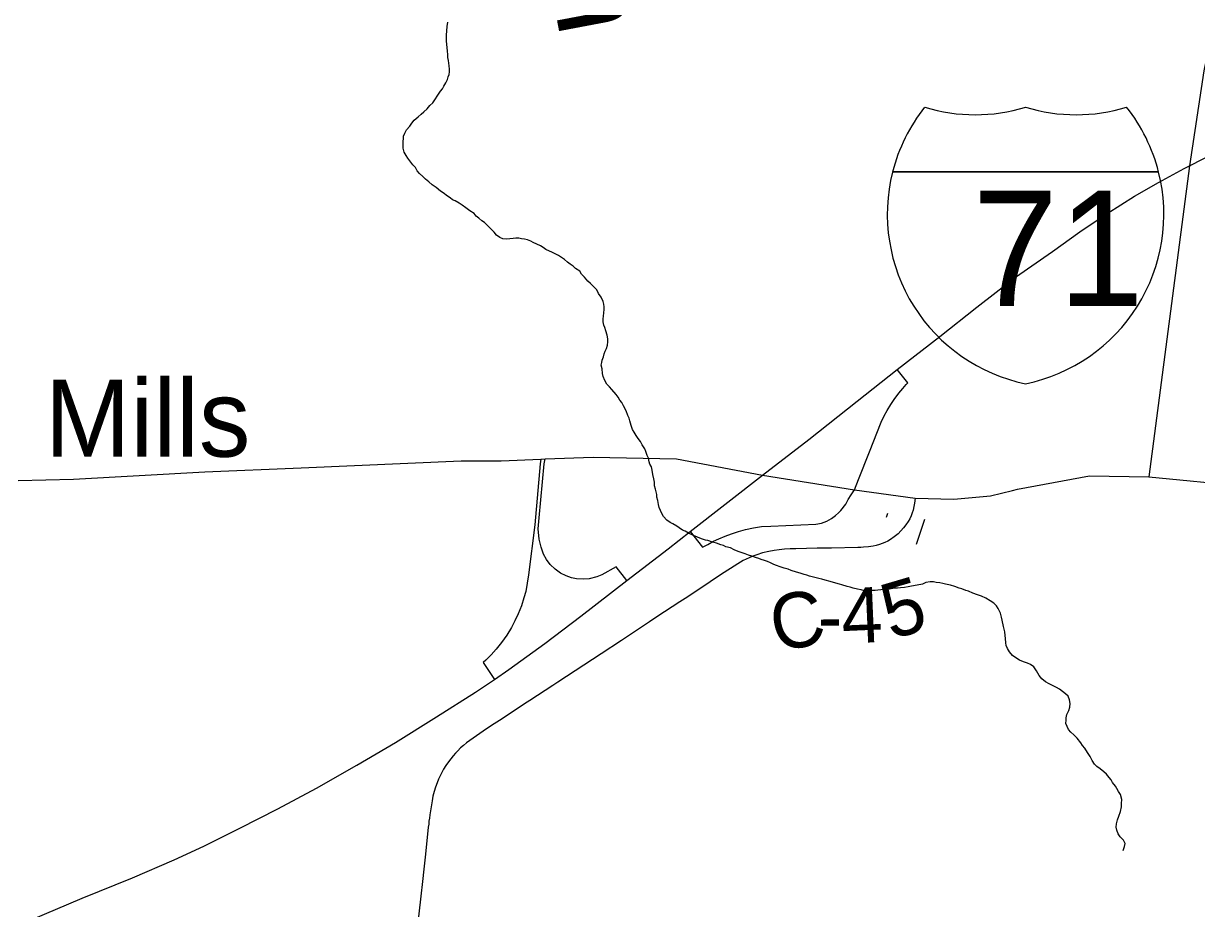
# Model space of a CAD drawing. Extents: x 0.4 to 34.4, y -2.1 to 19.9.
# Drawn here: x 4.197 to 5.402, y 14.193 to 15.102 of the extents above; entities that cross this region are included whole.
import ezdxf

# ---------------------------------------------------------------- set-up
doc = ezdxf.new("R2010")
doc.units = 0
for name, color, linetype in [('GM_X_County_Road', 7, 'Continuous'), ('GM_X_County_Road_Text', 7, 'Continuous'), ('GM_X_Interchange_Ramps', 7, 'Continuous'), ('GM_X_Interstate_Route', 7, 'Continuous'), ('GM_X_Interstate_Shield', 7, 'Continuous'), ('GM_X_Minor_River', 7, 'Continuous'), ('GM_X_Minor_River_Text', 7, 'Continuous'), ('GM_X_Unincorporated_Text', 7, 'Continuous')]:
    doc.layers.add(name, color=color, linetype=linetype)

msp = doc.modelspace()

# ---------------------------------------------------------------- linework, layer by layer
at = {"layer": 'GM_X_County_Road'}
for points in [[(5.1472, 16.0652), (5.1472, 16.0652), (5.1927, 15.4283), (5.1962, 15.413), (5.2017, 15.4034), (5.2182, 15.394), (5.4257, 15.3499), (5.4355, 15.3459), (5.4407, 15.3424), (5.4524, 15.2606), (5.4094, 15.0538), (5.3948, 14.9559)], [(5.3948, 14.9559), (5.3532, 14.6364)], [(5.3532, 14.6364), (5.551, 14.6173), (5.7946, 14.5981), (5.9549, 14.5868), (6.1689, 14.5743), (6.183, 14.58), (6.2787, 14.5749), (6.327, 14.5697), (6.3748, 14.5632), (6.4792, 14.5513), (6.6022, 14.5578), (6.6586, 14.5646), (6.9447, 14.6216), (6.9686, 14.6277), (7.0369, 14.6701), (7.058, 14.675), (7.1535, 14.6887)], [(4.191, 14.6326), (4.2481, 14.634), (4.383, 14.6414), (4.4819, 14.6455), (4.6462, 14.6527), (4.6594, 14.6528)], [(4.6594, 14.6528), (4.6875, 14.6529), (4.7282, 14.6546), (4.7326, 14.6548), (4.782, 14.6567), (4.8677, 14.6547), (4.9561, 14.6381)], [(4.9561, 14.6381), (5.0504, 14.6229), (5.1129, 14.6146), (5.1527, 14.6133), (5.1905, 14.617), (5.2131, 14.6224)], [(5.2131, 14.6224), (5.218, 14.6236), (5.2919, 14.6374), (5.3532, 14.6364)], [(5.1129, 14.6146), (5.1123, 14.6094), (5.1117, 14.6057), (5.1109, 14.6021), (5.1099, 14.5992), (5.1088, 14.5963), (5.1073, 14.5933), (5.1056, 14.5903), (5.1034, 14.587), (5.101, 14.5838), (5.0982, 14.5807), (5.0953, 14.5778), (5.0915, 14.5747), (5.0876, 14.572), (5.0847, 14.5703), (5.0819, 14.5689), (5.0791, 14.5677), (5.0761, 14.5667), (5.073, 14.5658), (5.0698, 14.565), (5.0648, 14.5643), (5.0597, 14.564), (5.0572, 14.5638), (5.0541, 14.5637), (5.0269, 14.5631), (5.0122, 14.5629), (4.9903, 14.5625), (4.9843, 14.5623), (4.9788, 14.5621), (4.9733, 14.5615), (4.9679, 14.5608), (4.9625, 14.5597), (4.9561, 14.5581), (4.9502, 14.5563), (4.9461, 14.5548), (4.9422, 14.5531), (4.9363, 14.5502), (4.9306, 14.5468), (4.9128, 14.5355), (4.9024, 14.5285), (4.8998, 14.5268), (4.8764, 14.5113), (4.8711, 14.5078), (4.8476, 14.4924), (4.845, 14.4906), (4.8424, 14.4889), (4.8398, 14.4872), (4.8163, 14.4717), (4.8111, 14.4683), (4.7902, 14.4546), (4.7457, 14.4254), (4.7405, 14.422), (4.717, 14.4065), (4.7143, 14.4048), (4.6856, 14.386), (4.6803, 14.3826), (4.6777, 14.3809), (4.6751, 14.3791), (4.6725, 14.3774), (4.6552, 14.3654), (4.6519, 14.363), (4.6488, 14.3604), (4.6457, 14.3577), (4.6428, 14.3549), (4.6404, 14.3523), (4.638, 14.3495), (4.6356, 14.3466), (4.6334, 14.3436), (4.6306, 14.3396), (4.6283, 14.3358), (4.6265, 14.3326), (4.6248, 14.3292), (4.6232, 14.3256), (4.6217, 14.3219), (4.62, 14.3174), (4.6186, 14.3128), (4.6174, 14.3081), (4.6165, 14.3033), (4.6141, 14.2888), (4.6137, 14.2857), (4.6133, 14.2826), (4.613, 14.2795), (4.6126, 14.2764), (4.6096, 14.2485), (4.6089, 14.2423), (4.6086, 14.2392), (4.606, 14.2144), (4.6057, 14.2114), (4.6046, 14.2022), (4.6014, 14.1754)]]:
    msp.add_lwpolyline(points, dxfattribs=at)
at = {"layer": 'GM_X_Interchange_Ramps'}
for points in [[(5.0504, 14.6229), (5.0547, 14.6335), (5.0661, 14.6621), (5.0779, 14.6924), (5.0811, 14.6989), (5.0841, 14.7045), (5.0878, 14.7106), (5.0914, 14.716), (5.0961, 14.7223), (5.1002, 14.7272), (5.1038, 14.7312), (5.1054, 14.7328), (5.0943, 14.7467)], [(4.7282, 14.6546), (4.7274, 14.6498), (4.7219, 14.587), (4.7157, 14.5356), (4.7127, 14.5186), (4.7109, 14.5119), (4.7082, 14.5037), (4.7049, 14.4954), (4.7016, 14.4882), (4.698, 14.4815), (4.6932, 14.4736), (4.6879, 14.466), (4.6825, 14.4593), (4.6773, 14.4535), (4.6717, 14.4478), (4.6689, 14.4454), (4.6805, 14.4282)], [(4.8166, 14.5299), (4.8057, 14.544), (4.7909, 14.5356), (4.7858, 14.5335), (4.7779, 14.5316), (4.7717, 14.5311), (4.765, 14.5315), (4.7599, 14.5326), (4.7543, 14.5345), (4.7484, 14.5375), (4.743, 14.5414), (4.7379, 14.5464), (4.7341, 14.5515), (4.731, 14.557), (4.7286, 14.5639), (4.7264, 14.5722), (4.7255, 14.5828), (4.7265, 14.5943), (4.7317, 14.6497), (4.7326, 14.6548)], [(4.8818, 14.5802), (4.8945, 14.5639), (4.8997, 14.5669), (4.9058, 14.5701), (4.9111, 14.5726), (4.9176, 14.5754), (4.9243, 14.5779), (4.9314, 14.5802), (4.9385, 14.5821), (4.9467, 14.5839), (4.9549, 14.5853), (4.9646, 14.5858), (5.011, 14.5877), (5.0165, 14.5888), (5.0221, 14.5909), (5.027, 14.5935), (5.031, 14.5965), (5.034, 14.5992), (5.0364, 14.6018), (5.0415, 14.6083), (5.0442, 14.6132), (5.0473, 14.618), (5.0504, 14.6229)]]:
    msp.add_lwpolyline(points, dxfattribs=at)
at = {"layer": 'GM_X_Interstate_Route'}
for points in [[(4.9561, 14.6381), (5.0038, 14.6747), (5.0534, 14.714), (5.0943, 14.7467), (5.1381, 14.7806), (5.1763, 14.8109), (5.216, 14.8416), (5.2541, 14.8681), (5.2823, 14.8883), (5.3101, 14.907), (5.3383, 14.9249), (5.3631, 14.939), (5.3894, 14.9532), (5.3948, 14.9559), (5.4385, 14.9781)], [(4.2044, 14.181), (4.2569, 14.2032), (4.3086, 14.2243), (4.3515, 14.2428), (4.382, 14.2566), (4.4189, 14.2751), (4.4581, 14.2952), (4.4977, 14.3164), (4.5392, 14.3399), (4.5788, 14.3633), (4.6211, 14.3898), (4.6611, 14.4152), (4.6805, 14.4282), (4.6954, 14.4383), (4.7324, 14.4652), (4.7695, 14.4933), (4.8166, 14.5299), (4.8591, 14.5625), (4.8818, 14.5802), (4.9561, 14.6381)]]:
    msp.add_lwpolyline(points, dxfattribs=at)
at = {"layer": 'GM_X_Interstate_Shield'}
for p, q in [((5.0898, 14.9497), (5.3631, 14.9497)), ((5.3631, 14.9497), (5.0898, 14.9497)), ((5.3631, 14.9497), (5.0898, 14.9497))]:
    msp.add_line(p, q, dxfattribs=at)
for centre, start, end in [((5.2619, 14.9061), 141.669, 165.8066), ((5.1746, 15.1861), 253.0091, 286.9909), ((5.2783, 15.1861), 253.0091, 286.9909), ((5.1909, 14.9061), 14.1934, 38.331), ((5.2619, 14.9061), 165.8066, 258.463), ((5.1909, 14.9061), 281.537, 14.1934)]:
    msp.add_arc(centre, 0.1776, start, end, dxfattribs=at)
at = {"layer": 'GM_X_Minor_River'}
for points in [[(4.5897, 14.9666), (4.5879, 14.9701), (4.5869, 14.9743), (4.5866, 14.9777), (4.5866, 14.9812), (4.5871, 14.9838), (4.5871, 14.9865), (4.5883, 14.9895), (4.5903, 14.9929), (4.5935, 14.9966), (4.5958, 15), (4.5982, 15.003), (4.6021, 15.0064), (4.6052, 15.009), (4.6079, 15.0116), (4.6114, 15.0146), (4.6141, 15.018), (4.6173, 15.0209), (4.62, 15.0247), (4.6216, 15.0277), (4.6251, 15.0326), (4.6271, 15.0352), (4.6287, 15.0379), (4.6307, 15.0412), (4.6323, 15.0446), (4.6331, 15.0473), (4.6339, 15.0499), (4.6344, 15.0526), (4.6344, 15.0553), (4.6341, 15.0587), (4.6338, 15.0614), (4.6335, 15.0644), (4.6328, 15.0675), (4.6325, 15.0705), (4.6322, 15.0739), (4.6316, 15.0812), (4.6313, 15.0842), (4.6313, 15.0873), (4.6314, 15.0903), (4.6315, 15.0949), (4.632, 15.0991), (4.6325, 15.1036)], [(4.816, 14.7041), (4.8131, 14.7095), (4.8113, 14.7126), (4.8094, 14.7153), (4.8076, 14.7184), (4.8057, 14.7211), (4.8013, 14.7261), (4.7987, 14.7288), (4.7961, 14.7315), (4.7939, 14.7353), (4.7924, 14.7396), (4.7917, 14.7426), (4.7911, 14.7472), (4.7904, 14.751), (4.7908, 14.7537), (4.7913, 14.7563), (4.7925, 14.7597), (4.7933, 14.7628), (4.7945, 14.7654), (4.7958, 14.7684), (4.7966, 14.7718), (4.797, 14.7752), (4.7971, 14.7783), (4.7964, 14.7821), (4.795, 14.7863), (4.7939, 14.7898), (4.7929, 14.7924), (4.7922, 14.7955), (4.7922, 14.7989), (4.7927, 14.8016), (4.7931, 14.805), (4.7932, 14.8084), (4.7933, 14.8111), (4.793, 14.8138), (4.7923, 14.8164), (4.7901, 14.821), (4.7875, 14.8249), (4.7857, 14.8287), (4.7831, 14.8314), (4.7793, 14.8349), (4.7767, 14.8376), (4.773, 14.8415), (4.77, 14.8446), (4.7682, 14.8477), (4.764, 14.8504), (4.7614, 14.8528), (4.7584, 14.8551), (4.7558, 14.8571), (4.7524, 14.8598), (4.7494, 14.8617), (4.7464, 14.8637), (4.743, 14.8657), (4.7396, 14.8672), (4.737, 14.8684), (4.7332, 14.87), (4.7306, 14.872), (4.728, 14.8739), (4.7242, 14.8755), (4.7204, 14.8771), (4.7178, 14.8787), (4.7144, 14.8799), (4.7113, 14.8807), (4.7083, 14.8811), (4.7056, 14.8816), (4.7026, 14.8816), (4.6999, 14.8813), (4.6965, 14.881), (4.6927, 14.8807), (4.6892, 14.8811), (4.6862, 14.8823), (4.6828, 14.8847), (4.6802, 14.8877), (4.6776, 14.8905), (4.6746, 14.8936), (4.6702, 14.8978), (4.6675, 14.8994), (4.6645, 14.9021), (4.6619, 14.9041), (4.6597, 14.9071), (4.6552, 14.9099), (4.6511, 14.913), (4.6473, 14.9157), (4.6443, 14.9177), (4.6402, 14.9201), (4.6375, 14.9212), (4.6349, 14.9232), (4.6323, 14.9248), (4.6278, 14.9283), (4.6251, 14.9298), (4.6206, 14.9337), (4.6165, 14.9365), (4.6131, 14.9396), (4.6098, 14.9423), (4.6068, 14.945), (4.6034, 14.9481), (4.6012, 14.9508), (4.5994, 14.9543), (4.5968, 14.957), (4.5945, 14.9597), (4.5916, 14.9639), (4.5897, 14.9666)], [(5.1021, 14.5227), (5.0979, 14.5224), (5.0949, 14.5221), (5.0918, 14.5218), (5.0884, 14.5214), (5.0849, 14.5207), (5.0811, 14.5204), (5.0777, 14.5201), (5.0746, 14.5198), (5.0719, 14.5195), (5.0693, 14.5195), (5.0654, 14.5196), (5.0609, 14.5193), (5.0575, 14.5201), (5.0537, 14.5209), (5.0491, 14.5218), (5.0461, 14.523), (5.043, 14.5238), (5.0377, 14.5254), (5.0351, 14.5262), (5.0313, 14.527), (5.0256, 14.5287), (5.0203, 14.5303), (5.0169, 14.5311), (5.0139, 14.5319), (5.0086, 14.5332), (5.0044, 14.5344), (5.0017, 14.5352), (4.9987, 14.536), (4.9949, 14.5372), (4.9911, 14.5384), (4.9855, 14.5401), (4.9824, 14.5413), (4.9783, 14.5425), (4.9741, 14.5437), (4.9703, 14.5453), (4.9677, 14.5461), (4.9643, 14.5481), (4.9613, 14.5493), (4.9582, 14.5504), (4.9548, 14.5513), (4.9522, 14.5525), (4.9488, 14.5533), (4.945, 14.5549), (4.9416, 14.5557), (4.9382, 14.5573), (4.9352, 14.5581), (4.931, 14.5597), (4.9268, 14.5613), (4.9231, 14.5633), (4.9185, 14.5645), (4.9159, 14.5657), (4.9132, 14.5665), (4.9087, 14.5681), (4.9045, 14.5693), (4.9, 14.5709), (4.8973, 14.5714), (4.8932, 14.5726), (4.8894, 14.5742), (4.8852, 14.5761), (4.8799, 14.5785), (4.8766, 14.5805), (4.8739, 14.5817), (4.8705, 14.584), (4.8679, 14.5856), (4.8638, 14.5879), (4.8611, 14.5895), (4.8578, 14.5919), (4.8544, 14.5957), (4.8522, 14.5992), (4.8511, 14.6019), (4.85, 14.6049), (4.849, 14.608), (4.8483, 14.6122), (4.8476, 14.6153), (4.8473, 14.6183), (4.8466, 14.621), (4.8459, 14.6237), (4.8452, 14.6271), (4.8449, 14.6309), (4.8442, 14.6343), (4.8432, 14.6386), (4.8425, 14.6431), (4.8418, 14.6466), (4.8404, 14.6493), (4.8397, 14.6519), (4.839, 14.6554), (4.8375, 14.6584), (4.8361, 14.6623), (4.835, 14.6653), (4.8324, 14.6692), (4.8306, 14.6727), (4.8284, 14.6757), (4.8262, 14.6788), (4.8243, 14.6823), (4.8225, 14.685), (4.821, 14.6892), (4.8196, 14.6938), (4.8189, 14.6965), (4.8178, 14.6995), (4.816, 14.7041)], [(5.3267, 14.2522), (5.328, 14.2564), (5.3288, 14.2594), (5.327, 14.2629), (5.3236, 14.2664), (5.3214, 14.2695), (5.3203, 14.2733), (5.3196, 14.2763), (5.3197, 14.2798), (5.3209, 14.2839), (5.3222, 14.2877), (5.3238, 14.2923), (5.3251, 14.2972), (5.3251, 14.3006), (5.3252, 14.3048), (5.3238, 14.3098), (5.322, 14.3128), (5.3201, 14.3159), (5.3187, 14.3186), (5.3157, 14.3221), (5.3142, 14.3248), (5.3124, 14.3275), (5.3094, 14.3309), (5.3068, 14.3333), (5.3031, 14.3364), (5.2997, 14.3387), (5.2971, 14.3411), (5.2949, 14.3449), (5.2927, 14.3488), (5.2901, 14.353), (5.2871, 14.3576), (5.2849, 14.3603), (5.2831, 14.363), (5.2794, 14.3676), (5.276, 14.3711), (5.273, 14.3738), (5.2704, 14.3766), (5.269, 14.3796), (5.2679, 14.3827), (5.268, 14.3861), (5.268, 14.3888), (5.2689, 14.3922), (5.2709, 14.3963), (5.2717, 14.3997), (5.2722, 14.4035), (5.2715, 14.407), (5.27, 14.4108), (5.2674, 14.4135), (5.2644, 14.4159), (5.2611, 14.4182), (5.258, 14.4198), (5.2547, 14.4217), (5.2505, 14.4237), (5.2467, 14.4257), (5.243, 14.4288), (5.2404, 14.4323), (5.2375, 14.4369), (5.2349, 14.4411), (5.2315, 14.4435), (5.2285, 14.4447), (5.2243, 14.4463), (5.2202, 14.4479), (5.2164, 14.4502), (5.213, 14.4526), (5.2097, 14.4564), (5.2078, 14.4599), (5.2064, 14.463), (5.2061, 14.4656), (5.2058, 14.4702), (5.2055, 14.4733), (5.2052, 14.4771), (5.2038, 14.4824), (5.2024, 14.4889), (5.2017, 14.492), (5.2007, 14.4962), (5.1981, 14.5012), (5.1966, 14.5039), (5.1936, 14.5066), (5.1899, 14.5089), (5.1854, 14.5117), (5.1812, 14.5137), (5.1771, 14.5152), (5.1721, 14.5169), (5.1676, 14.5188), (5.165, 14.5197), (5.1608, 14.5213), (5.1582, 14.5221), (5.1536, 14.5237), (5.1491, 14.5249), (5.1441, 14.5261), (5.1415, 14.5266), (5.1384, 14.5274), (5.1346, 14.5278), (5.1316, 14.5283), (5.1282, 14.5283), (5.124, 14.5276), (5.1205, 14.5262), (5.1148, 14.5251), (5.109, 14.5241), (5.1056, 14.5234), (5.1021, 14.5227)]]:
    msp.add_lwpolyline(points, dxfattribs=at)
at = {"layer": 'GM_X_Minor_River_Text'}
for p, q in [((5.0846, 14.5987), (5.0832, 14.5946)), ((5.1224, 14.5926), (5.1141, 14.5669))]:
    msp.add_line(p, q, dxfattribs=at)

# ---------------------------------------------------------------- texts
at = {"layer": 'GM_X_County_Road_Text'}
for s, rotation, p in [('5', 16.3929, (5.0881, 14.4688)), ('C', 10.7971, (4.9698, 14.4561)), ('4', 2.4479, (5.0382, 14.4649)), ('-', 0.7494, (5.0131, 14.4645))]:
    msp.add_text(s, height=0.0568, rotation=rotation, dxfattribs=at).set_placement(p)
at = {"layer": 'GM_X_Interstate_Shield'}
msp.add_text('71', height=0.11837, dxfattribs=at).set_placement((5.1718, 14.8121))
at = {"layer": 'GM_X_Minor_River_Text'}
msp.add_text('Branch', height=0.09472, rotation=280.7121, dxfattribs=at).set_placement((4.6739, 15.4807))
at = {"layer": 'GM_X_Unincorporated_Text'}
msp.add_text('Mathers Mills', height=0.078977, rotation=0, dxfattribs=at).set_placement((3.8077, 14.6571))

doc.saveas('drawing.dxf')
